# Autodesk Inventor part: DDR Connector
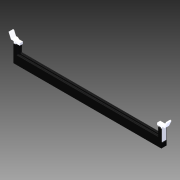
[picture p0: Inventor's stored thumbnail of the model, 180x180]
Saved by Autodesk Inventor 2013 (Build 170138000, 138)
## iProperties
Company: Autodesk Inc.
Created: 2005-11
Part Number: DDR Connector
Document SubType Name: Modeling
Designer: Autodesk Inc.
Stock Number: config - ram slot
Density: 1 g/cm^3
Mass: 5.26159 g
Surface Area: 74.6749 cm^2
Volume: 5.26159 cm^3
Material: Allgemein
Title: Personal Computer
Author: Autodesk Inc.
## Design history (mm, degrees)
sketch "Sketch1"
  geometry: L1 (0, 6)-(0, -1) reference; L2 (-28, 0)-(168, 0) reference; L3 (0, 0)-(140, 0); L4 (140, 0)-(140, 5); L5 (140, 5)-(0, 5); L6 (0, 5)-(0, 0)
  constraints: 8 end point, 2 parallel, 2 point on line, 1 horizontal, 1 perpendicular
  dimensions: "d0" = 140 distance of L4.end L5.end; "d1" = 5 distance of L3.end L4.end
extrude "Extrusion1" new body sketch "Sketch1" distance "d2" = 16; taper "d3" = 0 deg
sketch "Sketch2"
  geometry: L1 (0, 0)-(0, 5) reference; L2 (140, 5)-(140, 0) reference; L3 (0, 2.5)-(140, 2.5); L4 (0, 4.5)-(1.5, 4.5); L5 (1.5, 4.5)-(1.5, 0.5); L6 (1.5, 0.5)-(0, 0.5); L7 (0, 0.5)-(0, 4.5); L8 (140, 4.5)-(138.5, 4.5); L9 (138.5, 4.5)-(138.5, 0.5); L10 (138.5, 0.5)-(140, 0.5); L11 (140, 0.5)-(140, 4.5); L12 (1.8, 3)-(3, 3); L13 (3, 3)-(3, 2); L14 (3, 2)-(1.8, 2); L15 (1.8, 2)-(1.8, 3); L16 (138.2, 3)-(137, 3); L17 (137, 3)-(137, 2); L18 (137, 2)-(138.2, 2); L19 (138.2, 2)-(138.2, 3)
  constraints: 34 end point, 8 parallel, 4 equal length, 4 horizontal, 4 perpendicular, 2 midpoint, 2 point on line, 4 other
  dimensions: "d4" = 4 distance of L4.end L5.end; "d5" = 1.5 distance of L4.start L4.end; "d6" = 0.3 distance between parallel lines of L5 L15; "d7" = 1.2 distance of L13.end L14.end; "d8" = 1 distance of L12.end L13.end; "d9" = 0.3 distance between parallel lines of L9 L19 (= d6)
extrude "Extrusion2" cut sketch "Sketch2" distance "d10" = 12; taper "d11" = 0 deg
extrude "Extrusion3" cut sketch "Sketch2" distance "d12" = 10; taper "d13" = 0 deg
sketch "Sketch3"
  geometry: L1 (3, 3)-(3, 2) reference; L2 (137, 2)-(137, 3) reference; L3 (140, 0)-(0, 0) reference; L4 (0, 5)-(140, 5) reference; L5 (3, 5)-(137, 5); L6 (137, 5)-(137, 0); L7 (137, 0)-(3, 0); L8 (3, 0)-(3, 5)
  constraints: 8 end point, 2 collinear, 2 parallel, 2 point on line, 1 horizontal, 1 perpendicular
extrude "Extrusion4" cut sketch "Sketch3" distance "d14" = 8; taper "d15" = 0 deg
sketch "Sketch4"
  geometry: L1 (3, 5)-(3, 3) reference; L2 (3, 2)-(3, 3) reference; L3 (137, 3)-(137, 2) reference; L4 (137, 3)-(137, 5) reference; L5 (3, 2.5)-(137, 2.5); L6 (3, 3.5)-(4, 3.5); L7 (4, 3.5)-(4, 1.5); L8 (4, 1.5)-(3, 1.5); L9 (3, 1.5)-(3, 3.5); L10 (137, 3.765)-(136, 3.765); L11 (136, 3.765)-(136, 1.235); L12 (136, 1.235)-(137, 1.235); L13 (137, 1.235)-(137, 3.765)
  constraints: 18 end point, 5 parallel, 2 horizontal, 2 midpoint, 2 perpendicular, 2 point on line, 2 other
  dimensions: "d16" = 1 distance of L6.start L6.end; "d17" = 2 distance of L6.end L7.end
extrude "Extrusion5" cut sketch "Sketch4" stored distance "d18" = 8; taper "d19" = 0 deg
sketch "Sketch5"
  geometry: L1 (0, 0)-(0, 1) reference; L2 (10, 0)-(0, 0) reference; L3 (10, 1)-(10, 0) reference; L4 (10, 1)-(0, 1) reference; L5 (7, 1)-(7, 0)
  constraints: 2 end point, 2 point on line, 1 parallel, 1 perpendicular
  dimensions: "d20" = 3 distance between parallel lines of L3 L5
extrude "Extrusion6" cut sketch "Sketch5" stored distance "d21" = 8; taper "d22" = 0 deg
workplane "Work Plane1"
mirror "Mirror1"
sketch "Sketch6"
  geometry: L1 (4, 3.5)-(4, 1.5) reference; L2 (136, 1.235)-(136, 3.765) reference; L3 (4, 2.5)-(136, 2.5); L4 (4, 3)-(136, 3); L5 (136, 3)-(136, 2); L6 (136, 2)-(4, 2); L7 (4, 2)-(4, 3)
  constraints: 10 end point, 2 midpoint, 2 parallel, 2 point on line, 1 horizontal, 1 perpendicular, 1 other
  dimensions: "d23" = 1 distance between parallel lines of L6 L4
extrude "Extrusion7" cut sketch "Sketch6" distance "d24" = 3; taper "d25" = 0 deg
sketch "Sketch7"
  geometry: L1 (4, 3)-(136, 3) reference; L2 (3, 5)-(137, 5) reference; L3 (136, 2)-(4, 2) reference; L4 (4, 2)-(4, 1.5) reference; L5 (4, 1.5)-(3, 1.5) reference; L6 (3, 1.5)-(3, 0) reference; L7 (137, 0)-(3, 0) reference; L8 (137, 0)-(137, 1.235) reference; L9 (137, 1.235)-(136, 1.235) reference; L10 (136, 1.235)-(136, 2) reference; L11 (8.604, 5)-(8.604, 3); L12 (8.604, 2)-(8.604, 0); L13 (8.604, 4)-(7.692, 4); L14 (8.604, 1)-(8.024, 1); L15 (4.375, 4.6)-(4.625, 4.6); L16 (4.625, 4.6)-(4.625, 3.4); L17 (4.625, 3.4)-(4.375, 3.4); L18 (4.375, 3.4)-(4.375, 4.6); L19 (4.375, 1.6)-(4.625, 1.6); L20 (4.625, 1.6)-(4.625, 0.4); L21 (4.625, 0.4)-(4.375, 0.4); L22 (4.375, 0.4)-(4.375, 1.6); L23 (4, 3.5)-(4, 3) reference
  constraints: 24 end point, 5 parallel, 4 collinear, 4 perpendicular, 4 point on line, 2 horizontal, 2 midpoint, 2 other
  dimensions: "d26" = 1.2 distance of L15.end L16.end; "d28" = 0.25 distance of L15.start L15.end; "d37" = 0.375 distance between parallel lines of L23 L18
extrude "Extrusion8" cut sketch "Sketch7" distance "d29" = 2.5; taper "d30" = 0 deg
sketch "Sketch8"
  geometry: L1 (0.25, 0)-(0, 0) reference; L2 (0.25, 2.5)-(0.25, 0) reference; L3 (0, 2.5)-(0.25, 2.5) reference; L4 (0, 2.5)-(0, 0) reference; L5 (0, 2)-(0.25, 2)
  constraints: 2 end point, 2 point on line, 1 perpendicular
  dimensions: "d31" = 0.5 distance between parallel lines of L5 L3
extrude "Extrusion9" cut sketch "Sketch8" stored distance "d32" = 2; taper "d33" = 0 deg
sketch "Sketch9"
  geometry: L1 (0, 0)-(-1.5, 0) reference; L2 (0, 12)-(0, 0) reference; L3 (-1.5, 12)-(-1.5, 0) reference; L4 (-1, 1)-(-1, 13); L5 (0.5, 14.936)-(2, 14.936); L6 (2, 14.936)-(4, 19.436); L7 (5.097, 18.949)-(2.78, 13.736); L8 (2.78, 13.736)-(0.688, 13.736); L9 (0.2, 13)-(0.2, 1); L10 (5.097, 18.949)-(4, 19.436); L11 (0.2, 1)-(-1, 1); A1 r 2 centre (1, 13) between (0.5, 14.936) and (-1, 13); A2 r 0.8 centre (1, 13) between (0.688, 13.736) and (0.2, 13)
  constraints: 16 end point, 4 perpendicular, 4 point on circle, 2 centre point, 2 parallel, 1 tangent, 3 other
  dimensions: "d38" = 12 distance of L4.start L4.end; "d39" = 2 radius of A1; "d40" = 1.5 distance of L5.start L5.end; "d41" = 0.5 distance between parallel lines of L3 L4; "d42" = 1 distance from line of L1 L4.start; "d43" = 4.5 vertical distance of L5.end L6.end; "d44" = 3 distance from line of L4 L5.end; "d45" = 2 horizontal distance of L5.end L6.end; "d46" = 1.2 distance between parallel lines of L4 L9
extrude "Extrusion10" join sketch "Sketch9" stored distance "d47" = 10; taper "d48" = 0 deg
workplane "Work Plane3"
sketch "Sketch10"
  geometry: L1 (0, 0)-(0, 4) reference; L2 (0, 2)-(-3.348, 2); L3 (-1.25, 3.5)-(0.75, 3.5); L4 (0.75, 3.5)-(0.75, 0.5); L5 (0.75, 0.5)-(-1.25, 0.5); L6 (-1.25, 0.5)-(-1.25, 3.5); L7 (1, 0)-(1, 4) reference
  constraints: 10 end point, 2 parallel, 2 perpendicular, 1 horizontal, 1 midpoint, 1 other
  dimensions: "d51" = 3 distance of L5.end L3.start; "d52" = 2 distance of L3.start L3.end; "d55" = 0.25 distance between parallel lines of L7 L4
extrude "Extrusion11" join sketch "Sketch10" stored distance "d53" = 10; taper "d54" = 0 deg
workplane "Work Plane4"
mirror "Mirror2"
body "Solid1"
pattern_linear "Rectangular Pattern1" dims "d36" = 1
node "Projected Loop1"
other parameters: "d49" = 4
